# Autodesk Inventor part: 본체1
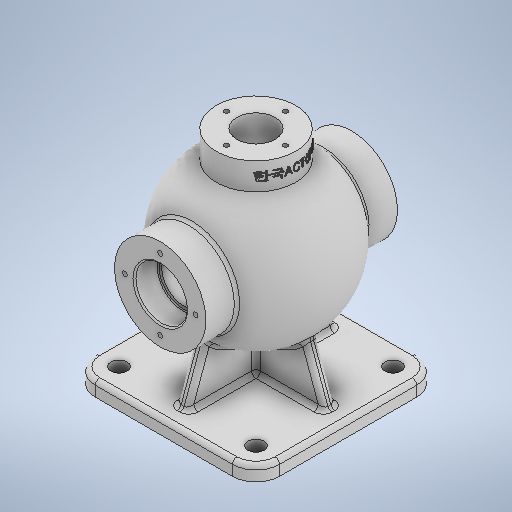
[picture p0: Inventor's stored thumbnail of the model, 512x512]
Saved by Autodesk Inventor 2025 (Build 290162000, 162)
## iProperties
Created: 2024-07
Part Number: 본체1
Material: 일반
Document SubType Name: Modeling
Designer: samsung
Density: 1 g/cm^3
Appearance: 기본값
Author: samsung
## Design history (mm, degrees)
sketch "스케치1"
  geometry: L1 (-46.5, -62.5)-(46.5, -62.5); L2 (62.5, -46.5)-(62.5, 46.5); L3 (46.5, 62.5)-(-46.5, 62.5); L4 (-62.5, 46.5)-(-62.5, -46.5); L5 (-62.5, -62.5)-(62.5, 62.5); L6 (62.5, -62.5)-(-62.5, 62.5); A1 r 16 centre (46.5, 46.5) between (62.5, 46.5) and (46.5, 62.5); A2 r 16 centre (-46.5, 46.5) between (-46.5, 62.5) and (-62.5, 46.5); A3 r 16 centre (-46.5, -46.5) between (-62.5, -46.5) and (-46.5, -62.5); A4 r 16 centre (46.5, -46.5) between (46.5, -62.5) and (62.5, -46.5); 1 further point
  constraints: 12 end point, 8 point on circle, 8 point on line, 8 tangent, 4 centre point, 3 equal radius, 2 midpoint, 2 parallel, 1 horizontal, 1 perpendicular
  dimensions: "d0" = 125 distance of L6.end L5.end; "d1" = 125 distance of L5.end L6.start; "d2" = 16 radius of A1
extrude "돌출1" new body sketch "스케치1" distance "d3" = 10; taper "d4" = 0 deg
sketch "스케치2"
  geometry: L1 (-46.5, 0)-(46.5, 0) reference; L2 (0, 139)-(0, 31); L3 (0, 139)-(0, 150.461); A1 r 54 centre (0, 85) between (0, 31) and (0, 139); A2 r 54 centre (0, 85) between (0, 139) and (0, 31); 3 further points
  constraints: 4 end point, 4 point on circle, 2 centre point, 2 midpoint, 2 vertical, 1 vertical alignment
  dimensions: "d5" = 108 diameter of A1; "d6" = 85 distance of point (0, 0) A1.centre; "d7" = 108 distance of L2.start L2.end
revolve "회전1" sketch "스케치2" stored, may be unused: angle "d8" = 90 deg
sketch "스케치3"
  geometry: C1 r 31 at (0, 85); 1 further point
  constraints: 1 centre point, 1 vertical alignment
  dimensions: "d9" = 62 diameter of C1; "d10" = 85 distance of point (0, 0) C1.centre
extrude "돌출2" join sketch "스케치3" stored distance "d11" = 130; taper "d12" = 0 deg
node "작업 평면1"
sketch "스케치4"
  geometry: C1 r 27 at (0, 0); 1 further point
  constraints: 1 centre point, 1 coincident
  dimensions: "d14" = 54 diameter of C1
extrude "돌출3" join sketch "스케치4" distance "d15" = 65; taper "d16" = 0 deg
sketch "스케치6"
  geometry: L1 (4, -50.5)-(-4, -50.5); L2 (-4, -50.5)-(-4, 50.5); L3 (-4, 50.5)-(4, 50.5); L4 (4, 50.5)-(4, -50.5); L5 (4, -50.5)-(-4, 50.5); L6 (-4, -50.5)-(4, 50.5); L7 (50.5, -4)-(-50.5, -4); L8 (-50.5, -4)-(-50.5, 4); L9 (-50.5, 4)-(50.5, 4); L10 (50.5, 4)-(50.5, -4); L11 (50.5, -4)-(-50.5, 4); L12 (-50.5, -4)-(50.5, 4); 6 further points
  constraints: 24 end point, 4 midpoint, 4 parallel, 2 horizontal, 2 perpendicular, 1 coincident
  dimensions: "d19" = 8 distance of L2.end L3.end; "d20" = 101 distance of L1.end L2.end; "d21" = 101 distance of L8.end L9.end; "d22" = 8 distance of L7.end L8.end
extrude "돌출4" join sketch "스케치6" distance "d23" = 75; taper "d24" = 0 deg
feature "면 기울기1" dims angle "d25" = 20 deg
feature "면 기울기2" dims angle "d26" = 20 deg
feature "면 기울기3" dims angle "d27" = 20 deg
feature "면 기울기4" dims angle "d28" = 20 deg
fillet "모깎기1" dims "d29" = 3
fillet "모깎기2" dims "d30" = 3
fillet "모깎기3" dims "d31" = 3
fillet "모깎기4" dims "d32" = 3
sketch "스케치7"
  geometry: L1 (46.5, 62.5)-(-46.5, 62.5) reference; L2 (62.5, -46.5)-(62.5, 46.5) reference; C1 r 5.5 at (46.5, 46.5); 1 further point
  constraints: 1 centre point
  dimensions: "d33" = 11 diameter of C1; "d34" = 16 distance from line of C1.centre L1; "d35" = 16 distance from line of L2 C1.centre
extrude "돌출5" cut sketch "스케치7" stored distance "d36" = 75; taper "d37" = 0 deg
sketch "스케치8"
  geometry: C1 r 31 at (0, 0) reference; C2 r 17.5 at (0, 0); 1 further point
  constraints: 1 centre point, 1 coincident
  dimensions: "d38" = 35 diameter of C2
extrude "돌출6" cut sketch "스케치8" distance "d39" = 16; taper "d40" = 0 deg
sketch "스케치9"
  geometry: C1 r 17.5 at (0, 0) reference; C2 r 15 at (0, 0); 1 further point
  constraints: 1 centre point, 1 coincident
  dimensions: "d45" = 30 diameter of C2
sketch "스케치10"
  geometry: L1 (0, 129)-(0, 41); L2 (0, 129)-(0, 137.625); A1 r 44 centre (0, 85) between (0, 41) and (0, 129); A2 r 44 centre (0, 85) between (0, 129) and (0, 41); 1 further point
  constraints: 4 end point, 4 point on circle, 2 centre point, 2 vertical, 1 vertical alignment
  dimensions: "d41" = 88 diameter of A1; "d42" = 85 distance of point (0, 0) A1.centre; "d43" = 88 distance of L1.start L1.end
revolve "회전2" sketch "스케치10" stored, may be unused: angle "d44" = 90 deg
extrude "돌출7" cut sketch "스케치9" stored distance "d46" = 10; taper "d47" = 0 deg
sketch "스케치11" dims "d48" = 48
  geometry: L1 (0, 0)-(0, 24); C1 r 17.5 at (0, 0) reference; 1 further point
  constraints: 2 end point, 1 coincident, 1 vertical, 1 vertical alignment, 2 other
hole "구멍1" sketch "스케치11" at (0, 24) diameter "d49" = 3.242; stored, may be unused: countersink angle "d53" = 82 deg, drill point angle "d55" = 120 deg; dims "d50" = 12, "d51" = 3.023, "d52" = 2, "d54" = 15
sketch "스케치12"
  geometry: C1 r 13 at (0, 0); 1 further point
  constraints: 1 centre point, 1 coincident
  dimensions: "d59" = 26 diameter of C1
extrude "돌출8" cut sketch "스케치12" stored distance "d60" = 10; taper "d61" = 0 deg
sketch "스케치13" dims "d62" = 40
  geometry: L1 (0, 0)-(0, 20); 1 further point
  constraints: 2 end point, 1 coincident, 1 vertical, 1 vertical alignment, 2 other
hole "구멍2" sketch "스케치13" at (0, 20) diameter "d63" = 3.242; stored, may be unused: countersink angle "d67" = 90 deg, drill point angle "d69" = 120 deg; dims "d64" = 9, "d65" = 4, "d66" = 2, "d68" = 11
chamfer "모따기1" distance "d73" = 1; stored, may be unused: second distance "d74" = 2, angle "d75" = 45 deg
fillet "모깎기5" dims "d76" = 0.6
fillet "모깎기6" dims "d77" = 3
node "작업 평면2"
sketch "스케치14"
  geometry: L1 (150, -27)-(150, 27) reference; 3 further points
  constraints: 1 horizontal alignment, 1 midpoint, 1 other
  dimensions: "d79" = 9 distance of point (150, 0) point (141, 0)
feature "엠보싱1" sketch "스케치14" dims "d6" = 85, "d80" = 0.5, "d81" = 0
fillet "모깎기7" dims "d82" = 3
node "솔리드1"
mirror "미러1"
mirror "미러2"
mirror "미러3"
pattern_circular "원형 패턴1" dims angle "d57" = 360 deg
mirror "미러4"
pattern_circular "원형 패턴2" dims angle "d71" = 360 deg
feature "A9D066F2-1C7D-4E18-AEED-F7BC21143FA4" dims "d49" = 3.242, "d50" = 12, "d51" = 3.023, "d52" = 2, "d53" = 82 deg, "d54" = 15, "d55" = 120 deg
other parameters: "d13" = 85, "d78" = 27
